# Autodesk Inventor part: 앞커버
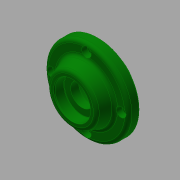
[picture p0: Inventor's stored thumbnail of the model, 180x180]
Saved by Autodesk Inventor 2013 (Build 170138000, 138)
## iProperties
Created: 2017-08
Part Number: 앞커버
Material: 알루미늄 6061
Document SubType Name: Modeling
Designer: mduedu
Density: 1 g/cm^3
Author: mduedu
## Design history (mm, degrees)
sketch "스케치1"
  geometry: C1 r 35 at (0, 0); 1 further point
  constraints: 1 centre point, 1 coincident
  dimensions: "d0" = 70 diameter of C1
extrude "돌출1" new body sketch "스케치1" distance "d1" = 10; taper "d2" = 0 deg
sketch "스케치2"
  geometry: C1 r 24 at (0, 0); 1 further point
  constraints: 1 centre point, 1 coincident
  dimensions: "d3" = 48 diameter of C1
node "작업 평면1"
sketch "스케치3"
  geometry: C1 r 20 at (0, 0); 1 further point
  constraints: 1 centre point, 1 coincident
  dimensions: "d5" = 40 diameter of C1
feature "로프트1" sketch "스케치3" dims "d6" = 0, "d7" = 90 deg, "d8" = 0, "d9" = 90 deg
sketch "스케치4"
  geometry: C1 r 24 at (0, 0) reference; 1 further point
extrude "돌출2" join sketch "스케치4" distance "d10" = 8; taper "d11" = 0 deg
hole "구멍1" diameter "d14" = 40; stored, may be unused: countersink angle "d18" = 90 deg, drill point angle "d20" = 0 deg; dims "d12" = 10, "d13" = 10, "d15" = 6, "d16" = 4, "d17" = 2, "d19" = 12
hole "구멍2" diameter "d23" = 34; stored, may be unused: countersink angle "d27" = 90 deg, drill point angle "d29" = 0 deg; dims "d21" = 10, "d22" = 10, "d24" = 6, "d25" = 4, "d26" = 2, "d28" = 3
hole "구멍3" diameter "d32" = 19; stored, may be unused: countersink angle "d36" = 90 deg, drill point angle "d38" = 0 deg; dims "d30" = 10, "d31" = 10, "d33" = 6, "d34" = 4, "d35" = 2, "d37" = 3
chamfer "모따기1" distance "d39" = 1; stored, may be unused: second distance "d40" = 2, angle "d41" = 45 deg
sketch "스케치5"
  geometry: C1 r 15 at (0, 0); 1 further point
  constraints: 1 centre point, 1 coincident
  dimensions: "d42" = 30 diameter of C1
extrude "돌출3" cut sketch "스케치5" distance "d43" = 8.3; taper "d44" = 0 deg
chamfer "모따기2" distance "d47" = 0.8; stored, may be unused: second distance "d48" = 2, angle "d49" = 30 deg
fillet "모깎기1" dims "d50" = 0.3
fillet "모깎기2" dims "d51" = 0.3
fillet "모깎기3" dims "d52" = 3
sketch "스케치6" dims "d53" = 58
  geometry: 6 further points
  constraints: 2 vertical alignment, 1 coincident, 7 other
  dimensions: "d56" = 360 deg dimension on point (0, 0) point (0, 29) (derived)
sketch "스케치9"
  geometry: 4 further points
  constraints: 4 other
hole "구멍6" sketch "스케치9" at (-29, 0), (0, -29), (29, 0), (0, 29) diameter "d72" = 4.5; stored, may be unused: countersink angle "d76" = 90 deg, drill point angle "d78" = 0 deg; dims "d73" = 6, "d74" = 8, "d75" = 4.6, "d77" = 8
fillet "모깎기4" dims "d79" = 3
fillet "모깎기5" dims "d80" = 3
fillet "모깎기6" dims "d81" = 3
chamfer "모따기3" distance "d82" = 1; stored, may be unused: second distance "d83" = 2, angle "d84" = 30 deg
node "솔리드1"
other parameters: "d4" = 12
